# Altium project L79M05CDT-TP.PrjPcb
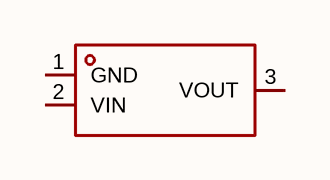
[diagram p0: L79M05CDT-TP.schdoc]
1 sheet, 1 parts. Net scope: global (net labels, ports and power ports of the same name join across sheets).

## Sheet L79M05CDT-TP.schdoc
size 127 x 101 mm

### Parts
U?  l79m05cdt-tp  [TO-252-2_L6.6-W6.1-P4.57-LS10.0-BR-CW]  (value not drawn)

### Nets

Not connected (* = marked no-connect by the designer): U? 1(GND) 2(VIN) 3(VOUT)

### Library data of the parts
U? = l79m05cdt-tp: 输出极性:负极;工作电压:35V;输出电压:5V;输出电流:500mA;电源纹波抑制比(PSRR):60dB;输出类型:固定;; Manufacturer: TECH PUBLIC(台舟); AddInBom: yes; ModelId: 16697a7febd74ea38893a430a7be29f0; ModelTransform: 393.7,259.842,0,0,0,0,-34.45,-0.005,0; Output Configuration: 负极; Voltage - Supply: 35V; Output Voltage: 5V; Output Current: 500mA; Power Supply Rejection Ratio (PSRR): 60dB; Voltage Dropout: 2V@(350mA); standby current: 1.5mA; Noise: 200uV; Output Type: 固定; Number of Outputs: 1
